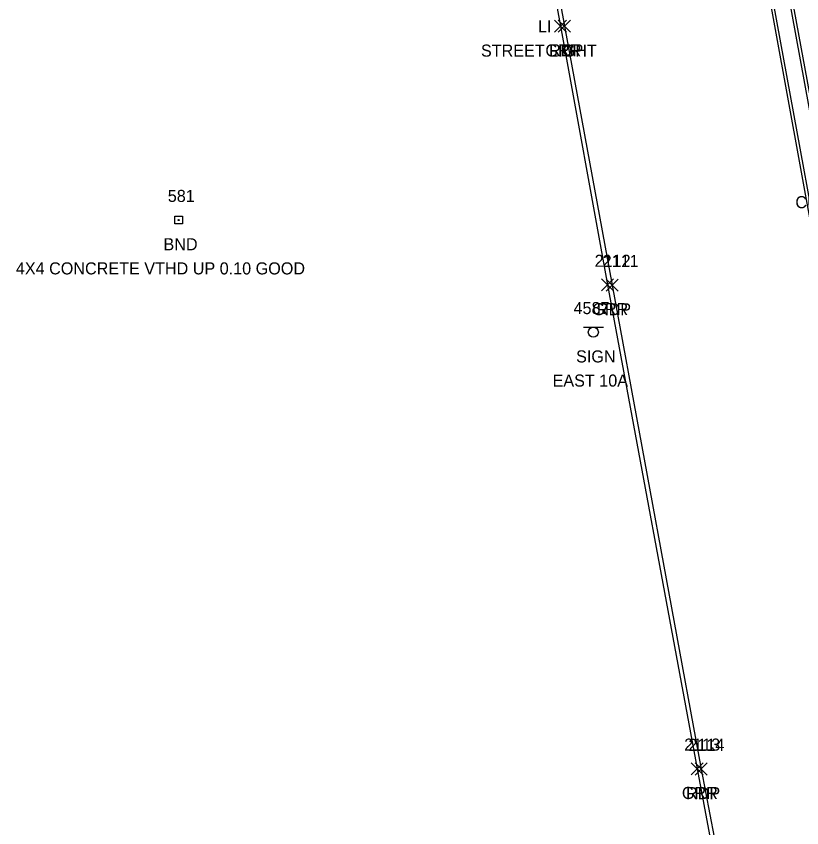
# Model space of a CAD drawing. Extents: x 1690689 to 1696275, y 438760 to 444007.
# Drawn here: x 1691306.8 to 1691436.8, y 440051.3 to 440185.6 of the extents above; entities that cross this region are included whole.
import ezdxf

# ---------------------------------------------------------------- set-up
doc = ezdxf.new("R2010")
doc.units = 0
for name, color, linetype in [('Level 18', 7, 'Continuous'), ('M_A', 7, 'Continuous'), ('M_C', 7, 'Continuous'), ('M_I', 7, 'Continuous'), ('P_A', 7, 'Continuous'), ('P_I', 7, 'Continuous'), ('P_TIC', 7, 'Continuous'), ('PET', 7, 'Continuous'), ('R_A', 7, 'Continuous'), ('R_I', 7, 'Continuous'), ('R_TIC', 7, 'Continuous'), ('RC', 7, 'Continuous'), ('RGR', 7, 'Continuous'), ('S_A', 7, 'Continuous'), ('S_C', 7, 'Continuous'), ('S_I', 7, 'Continuous'), ('SSGN', 7, 'Continuous'), ('U_A', 7, 'Continuous'), ('U_C', 7, 'Continuous')]:
    doc.layers.add(name, color=color, linetype=linetype)

msp = doc.modelspace()

# ---------------------------------------------------------------- linework, layer by layer
at = {"layer": 'Level 18'}
msp.add_lwpolyline([(1691333.06, 440152.51), (1691334.31, 440152.51), (1691334.31, 440151.26), (1691333.06, 440151.26)], close=True, dxfattribs=at)
msp.add_circle((1691333.69, 440151.89), 0.0833, dxfattribs=at)
at = {"layer": 'P_TIC'}
for points in [[(1691396.52, 440182.99), (1691398.52, 440184.99)], [(1691398.52, 440182.99), (1691396.52, 440184.99)], [(1691404.42, 440140.12), (1691406.42, 440142.12)], [(1691406.42, 440140.12), (1691404.42, 440142.12)], [(1691419.18, 440060.02), (1691421.18, 440062.02)], [(1691421.18, 440060.02), (1691419.18, 440062.02)]]:
    msp.add_lwpolyline(points, dxfattribs=at)
at = {"layer": 'PET'}
for points in [[(1691524.14, 439803.51), (1691505.35, 439875.13), (1691482.55, 439963.08), (1691466.38, 440025.17), (1691459.8, 440054.17), (1691452.22, 440095.05), (1691440.7, 440158.97), (1691412.63, 440311.4), (1691411.88, 440312.78), (1691410.59, 440313.02), (1691409.41, 440312.1), (1691409.25, 440309.98), (1691430.47, 440194.09), (1691444.44, 440117.42), (1691456.19, 440053.68), (1691471.28, 439973.47), (1691483.13, 439908.18), (1691494.09, 439857.01), (1691500.53, 439831.34)], [(1691377.54, 440285.07), (1691383.03, 440263.99), (1691389.71, 440226.83), (1691397.52, 440183.99), (1691405.42, 440141.12), (1691420.18, 440061.02), (1691427.31, 440023.49), (1691441.11, 439949.89), (1691451.37, 439894.72), (1691461.75, 439846.42), (1691469.53, 439815.36), (1691477.9, 439786.08), (1691489.83, 439749.54), (1691508.6, 439697.41), (1691528.81, 439647.65), (1691555.7, 439590.13)]]:
    msp.add_lwpolyline(points, dxfattribs=at)
at = {"layer": 'R_TIC'}
for points in [[(1691395.89, 440182.97), (1691397.89, 440184.97)], [(1691397.89, 440182.97), (1691395.89, 440184.97)], [(1691403.66, 440140.15), (1691405.66, 440142.15)], [(1691405.66, 440140.15), (1691403.66, 440142.15)], [(1691418.49, 440060.06), (1691420.49, 440062.06)], [(1691420.49, 440060.06), (1691418.49, 440062.06)]]:
    msp.add_lwpolyline(points, dxfattribs=at)
at = {"layer": 'RC'}
msp.add_lwpolyline([(1691458.4, 440056.24), (1691458.4, 440059.93), (1691451.63, 440094.87), (1691440.17, 440158.85), (1691412.32, 440311.04), (1691411.52, 440312.24), (1691410.74, 440312.52), (1691409.71, 440311.62), (1691430.98, 440193.93), (1691443.85, 440123.78), (1691455.79, 440058.61), (1691457.31, 440055.96)], dxfattribs=at)
at = {"layer": 'RGR'}
msp.add_lwpolyline([(1691377.05, 440284.73), (1691382.32, 440263.95), (1691388.93, 440226.77), (1691396.89, 440183.97), (1691404.66, 440141.15), (1691419.49, 440061.06), (1691426.89, 440021.5), (1691440.31, 439950.53), (1691450.78, 439894.67), (1691460.99, 439846.23), (1691468.83, 439815.05), (1691476.97, 439785.63), (1691488.62, 439749.74), (1691507.91, 439696.82), (1691528.09, 439647.02), (1691554.98, 439589.81)], dxfattribs=at)
at = {"layer": 'SSGN'}
for p, q in [((1691400.67, 440134.17), (1691404.01, 440134.17)), ((1691402.32, 440133.34), (1691402.32, 440133.34))]:
    msp.add_line(p, q, dxfattribs=at)
msp.add_circle((1691402.32, 440133.34), 0.833, dxfattribs=at)

# ---------------------------------------------------------------- texts
at = {"layer": 'M_A'}
msp.add_text('BND', height=2, dxfattribs=at).set_placement((1691331.18, 440146.89))
at = {"layer": 'M_C'}
msp.add_text('4X4 CONCRETE VTHD UP 0.10 GOOD', height=2, dxfattribs=at).set_placement((1691306.75, 440142.89))
at = {"layer": 'M_I'}
msp.add_text('581', height=2, dxfattribs=at).set_placement((1691331.89, 440154.89))
at = {"layer": 'P_A'}
for p in [(1691395, 440178.99), (1691402.91, 440136.12), (1691417.66, 440056.02)]:
    msp.add_text('RDP', height=2, dxfattribs=at).set_placement(p)
at = {"layer": 'P_I'}
for s, p in [('2111', (1691403.86, 440144.12)), ('2114', (1691418.05, 440064.02))]:
    msp.add_text(s, height=2, dxfattribs=at).set_placement(p)
at = {"layer": 'R_A'}
for s, p in [('GRR', (1691394.38, 440178.97)), ('CURBG', (1691435.75, 440153.85)), ('GRR', (1691402.15, 440136.15)), ('GRR', (1691416.97, 440056.06))]:
    msp.add_text(s, height=2, dxfattribs=at).set_placement(p)
at = {"layer": 'R_I'}
for s, p in [('2112', (1691402.54, 440144.15)), ('2113', (1691417.36, 440064.06))]:
    msp.add_text(s, height=2, dxfattribs=at).set_placement(p)
at = {"layer": 'S_A'}
msp.add_text('SIGN', height=2, dxfattribs=at).set_placement((1691399.46, 440128.32))
at = {"layer": 'S_C'}
msp.add_text('EAST 10A', height=2, dxfattribs=at).set_placement((1691395.57, 440124.32))
at = {"layer": 'S_I'}
msp.add_text('4587', height=2, dxfattribs=at).set_placement((1691399.04, 440136.32))
at = {"layer": 'U_A'}
msp.add_text('LI', height=2, dxfattribs=at).set_placement((1691393.16, 440182.94))
at = {"layer": 'U_C'}
msp.add_text('STREET LIGHT', height=2, dxfattribs=at).set_placement((1691383.72, 440178.94))

doc.saveas('drawing.dxf')
